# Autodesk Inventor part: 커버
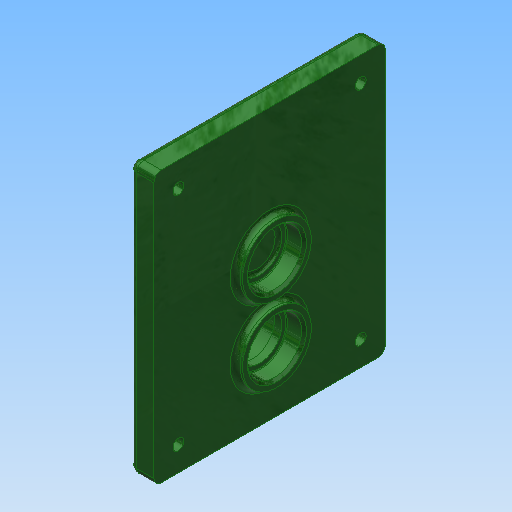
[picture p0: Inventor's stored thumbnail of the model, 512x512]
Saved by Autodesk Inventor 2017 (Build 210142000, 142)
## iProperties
Created: 2016-02
Part Number: 커버
Material: 알루미늄 6061
Document SubType Name: Modeling
Designer: mduedu
Density: 2.71 g/cm^3
Appearance: 매끄러움 - 짙은 산림 녹색
Mass: 271.622 g
Surface Area: 265.357 cm^2
Volume: 100.229 cm^3
Author: mduedu
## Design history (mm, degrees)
sketch "스케치1"
  geometry: L1 (63, 47)-(-47, 47); L2 (-47, 47)-(-47, -47); L3 (-47, -47)-(63, -47); L4 (63, -47)-(63, 47); 2 further points
  constraints: 8 end point, 2 parallel, 1 horizontal, 1 horizontal alignment, 1 midpoint, 1 perpendicular
  dimensions: "d102" = 94 distance of L3.end L1.start; "d104" = 47 distance from line of L2 point (0, 0); "d105" = 110 distance of L1.start L1.end
extrude "돌출1" new body sketch "스케치1" distance "d1" = 10; taper "d2" = 0 deg
sketch "스케치2"
  geometry: C1 r 14 at (0, 11); 1 further point
  constraints: 1 centre point, 1 vertical alignment
  dimensions: "d3" = 28 diameter of C1; "d6" = 11 distance of C1.centre point (0, 0)
extrude "돌출2" join sketch "스케치2" distance "d7" = 3; taper "d8" = 0 deg
sketch "스케치3"
  geometry: C1 r 14 at (0, -20); 1 further point
  constraints: 1 centre point, 1 vertical alignment
  dimensions: "d9" = 28 diameter of C1; "d10" = 20 distance of C1.centre point (0, 0)
extrude "돌출3" join sketch "스케치3" distance "d11" = 3; taper "d12" = 0 deg
hole "구멍1" diameter "d15" = 22; stored, may be unused: countersink angle "d19" = 90 deg, drill point angle "d21" = 0 deg; dims "d13" = 10, "d14" = 10, "d16" = 6, "d17" = 4, "d18" = 2, "d20" = 7
hole "구멍2" diameter "d24" = 18; stored, may be unused: countersink angle "d28" = 90 deg, drill point angle "d30" = 0 deg; dims "d22" = 10, "d23" = 10, "d25" = 6, "d26" = 4, "d27" = 2, "d29" = 1
hole "구멍3" diameter "d33" = 22; stored, may be unused: countersink angle "d37" = 90 deg, drill point angle "d39" = 0 deg; dims "d34" = 6, "d35" = 4, "d36" = 2, "d38" = 7, "d73" = 10, "d74" = 10
sketch "스케치4"
  geometry: C1 r 14 at (0, -20) reference; C2 r 18 at (0, -20); 1 further point
  constraints: 1 centre point, 1 coincident
  dimensions: "d40" = 36 diameter of C2
extrude "돌출4" join sketch "스케치4" distance "d41" = 4; taper "d42" = 0 deg
hole "구멍4" diameter "d45" = 22; stored, may be unused: countersink angle "d49" = 90 deg, drill point angle "d51" = 0 deg; dims "d43" = 10, "d44" = 10, "d46" = 6, "d47" = 4, "d48" = 2, "d50" = 7
hole "구멍5" diameter "d54" = 18; stored, may be unused: countersink angle "d58" = 90 deg, drill point angle "d60" = 0 deg; dims "d55" = 6, "d56" = 4, "d57" = 2, "d59" = 7, "d116" = 10, "d117" = 10
fillet "모깎기1" dims "d61" = 0.3
fillet "모깎기2" dims "d62" = 2
chamfer "모따기1" distance "d63" = 1; stored, may be unused: second distance "d64" = 2, angle "d65" = 45 deg
fillet "모깎기6" dims "d88" = 2
fillet "모깎기4" dims "d75" = 2
sketch "스케치9"
  geometry: L1 (47, 63)-(47, -47) reference; L2 (-47, 63)-(47, 63) reference; L3 (-47, -47)-(-47, 63) reference; L4 (47, -47)-(-47, -47) reference; L5 (37, 53)-(37, -37); L6 (37, -37)-(-37, -37); L7 (-37, -37)-(-37, 53); L8 (-37, 53)-(37, 53); C1 r 20 at (0, -20) reference; 5 further points
  constraints: 8 end point, 4 coincident, 3 other
  dimensions: "d107" = 10 distance between parallel lines of L8 L2
hole "구멍7" sketch "스케치9" at (-37, 53), (37, 53), (37, -37), (-37, -37) diameter "d108" = 4.5; stored, may be unused: countersink angle "d112" = 90 deg, drill point angle "d114" = 118 deg; dims "d109" = 6, "d110" = 8, "d111" = 4.6, "d113" = 8
fillet "모깎기8" dims "d106" = 3
fillet "모깎기9" dims "d115" = 3
node "솔리드1"
node "투영된 루프2"
